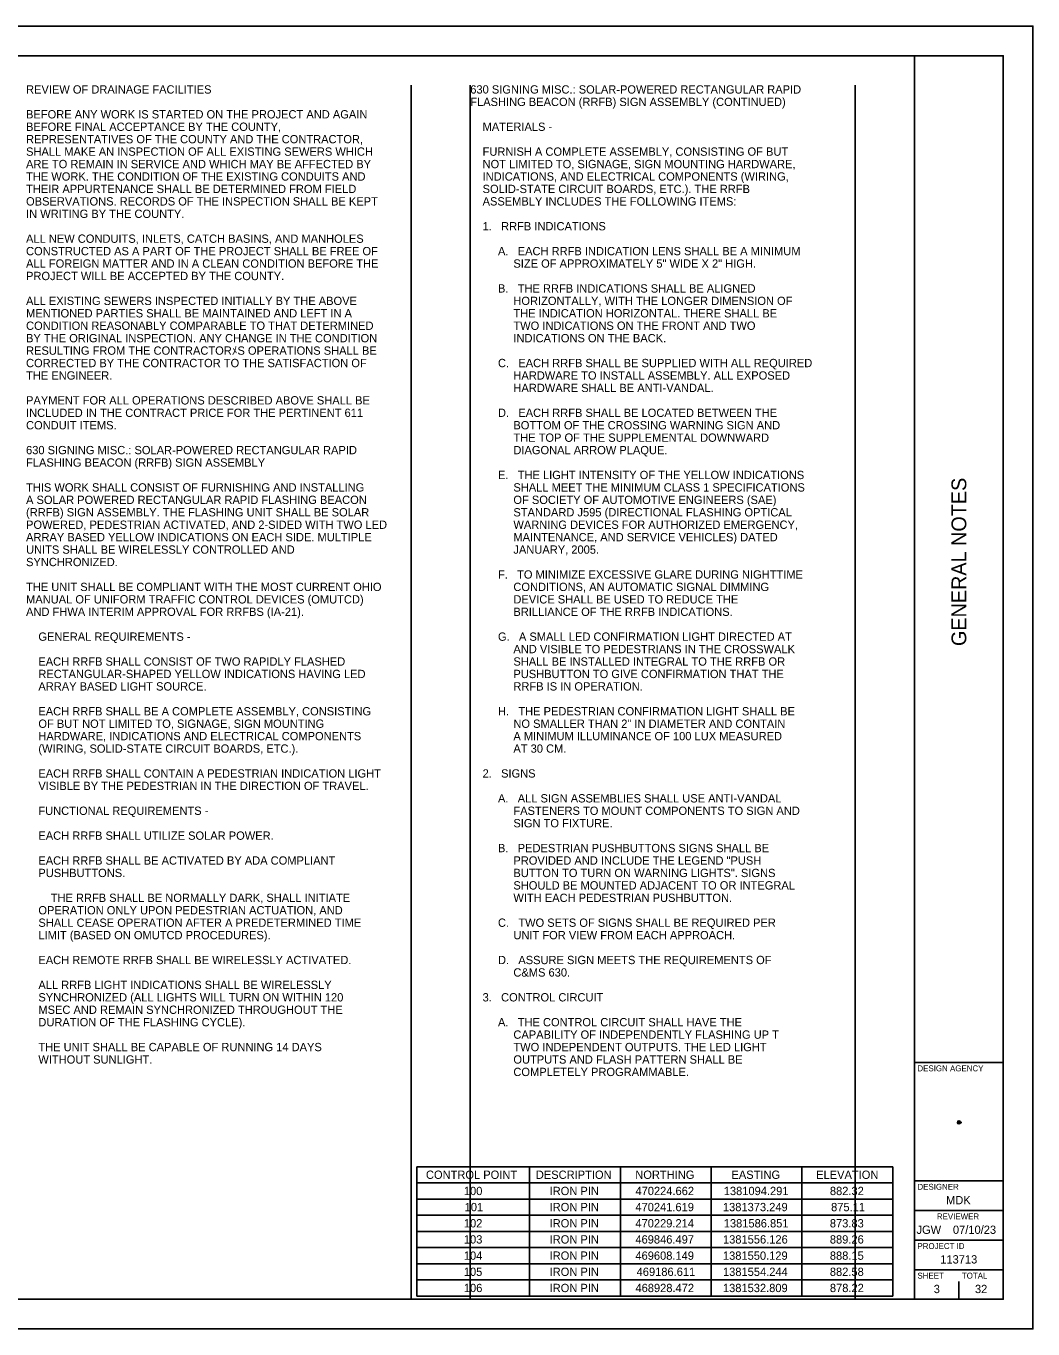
# Model space of a CAD drawing. Extents: x -8.5 to 44.5, y -22.3 to 22.
# Drawn here: x 17 to 34, y 0 to 22 of the extents above; entities that cross this region are included whole.
import ezdxf

# ---------------------------------------------------------------- set-up
doc = ezdxf.new("R2010")
doc.units = 0
for name, color, linetype in [('Default', 7, 'Continuous'), ('SN_X_Public', 7, 'Continuous'), ('SV_P_Mon_Cells_Set', 7, 'Continuous'), ('SV_X_Mon_Cells_Found', 7, 'Continuous'), ('SV_X_Random_Point', 7, 'Continuous'), ('SV_X_Shot_Marker', 7, 'Continuous')]:
    doc.layers.add(name, color=color, linetype=linetype)

msp = doc.modelspace()

# ---------------------------------------------------------------- linework, layer by layer
at = {"layer": 'Default'}
for p, q in [((32.724, 3.488), (32.776, 3.488)), ((32.75, 3.488), (32.799, 3.488))]:
    msp.add_line(p, q, dxfattribs=at)
msp.add_circle((32.75, 3.488), 0.026, dxfattribs=at)
at = {"layer": 'SN_X_Public'}
for p, q in [((23.5, 21), (23.5, 0.5)), ((24.5, 21), (24.5, 0.5)), ((31, 21), (31, 0.5))]:
    msp.add_line(p, q, dxfattribs=at)
at = {"layer": 'SV_P_Mon_Cells_Set'}
msp.add_lwpolyline([(0, 0), (34, 0), (34, 22), (0, 22)], close=True, dxfattribs=at)
at = {"layer": 'SV_X_Mon_Cells_Found'}
for p, q in [((32, 0.5), (32, 21.5)), ((32, 4.5), (33.5, 4.5)), ((32, 2.5), (33.5, 2.5)), ((32, 2), (33.5, 2)), ((32, 1.5), (33.5, 1.5)), ((32, 1), (33.5, 1))]:
    msp.add_line(p, q, dxfattribs=at)
msp.add_lwpolyline([(1.5, 21.5), (33.5, 21.5), (33.5, 0.5), (1.5, 0.5)], close=True, dxfattribs=at)
at = {"layer": 'SV_X_Random_Point'}
for p, q in [((23.6, 2.74), (31.633, 2.74)), ((23.6, 2.74), (23.6, 0.556)), ((25.5, 2.74), (25.5, 0.556)), ((27.034, 2.74), (27.034, 0.556)), ((28.566, 2.74), (28.566, 0.556)), ((30.099, 2.74), (30.099, 0.556)), ((31.633, 2.74), (31.633, 0.556)), ((23.6, 2.467), (31.633, 2.467)), ((23.6, 2.194), (31.633, 2.194)), ((23.6, 1.921), (31.633, 1.921)), ((23.6, 1.648), (31.633, 1.648)), ((23.6, 1.375), (31.633, 1.375)), ((23.6, 1.102), (31.633, 1.102)), ((23.6, 0.829), (31.633, 0.829)), ((23.6, 0.556), (31.633, 0.556))]:
    msp.add_line(p, q, dxfattribs=at)
at = {"layer": 'SV_X_Shot_Marker'}
for p, q in [((32.75, 3.5), (32.75, 3.5)), ((32.375, 0.675), (32.375, 0.675)), ((32.75, 0.5), (32.75, 0.8))]:
    msp.add_line(p, q, dxfattribs=at)

# ---------------------------------------------------------------- texts
at = {"layer": 'Default'}
for s, p in [('1', (32.749, 3.495)), ('3', (32.749, 3.478)), ('Drawing', (32.782, 3.495)), ('1:1', (32.782, 3.478))]:
    msp.add_text(s, height=0.00328, dxfattribs=at).set_placement(p)
at = {"layer": 'SV_X_Random_Point'}
for s, p in [('REVIEW OF DRAINAGE FACILITIES', (17, 20.86)), ('630 SIGNING MISC.: SOLAR-POWERED RECTANGULAR RAPID', (24.5, 20.86)), ('FLASHING BEACON (RRFB) SIGN ASSEMBLY (CONTINUED)', (24.5, 20.65)), ('BEFORE ANY WORK IS STARTED ON THE PROJECT AND AGAIN ', (17, 20.44)), ('BEFORE FINAL ACCEPTANCE BY THE COUNTY, ', (17, 20.23)), ('    MATERIALS -', (24.5, 20.23)), ('REPRESENTATIVES OF THE COUNTY AND THE CONTRACTOR, ', (17, 20.02)), ('SHALL MAKE AN INSPECTION OF ALL EXISTING SEWERS WHICH ', (17, 19.81)), ('    FURNISH A COMPLETE ASSEMBLY, CONSISTING OF BUT', (24.5, 19.81)), ('ARE TO REMAIN IN SERVICE AND WHICH MAY BE AFFECTED BY ', (17, 19.6)), ('    NOT LIMITED TO, SIGNAGE, SIGN MOUNTING HARDWARE,', (24.5, 19.6)), ('THE WORK. THE CONDITION OF THE EXISTING CONDUITS AND ', (17, 19.39)), ('    INDICATIONS, AND ELECTRICAL COMPONENTS (WIRING,', (24.5, 19.39)), ('THEIR APPURTENANCE SHALL BE DETERMINED FROM FIELD ', (17, 19.18)), ('    SOLID-STATE CIRCUIT BOARDS, ETC.). THE RRFB', (24.5, 19.18)), ('OBSERVATIONS. RECORDS OF THE INSPECTION SHALL BE KEPT ', (17, 18.97)), ('    ASSEMBLY INCLUDES THE FOLLOWING ITEMS:', (24.5, 18.97)), ('IN WRITING BY THE COUNTY.', (17, 18.76)), ('ALL NEW CONDUITS, INLETS, CATCH BASINS, AND MANHOLES ', (17, 18.34)), ('    1.   RRFB INDICATIONS', (24.5, 18.55)), ('CONSTRUCTED AS A PART OF THE PROJECT SHALL BE FREE OF ', (17, 18.13)), ('         A.   EACH RRFB INDICATION LENS SHALL BE A MINIMUM', (24.5, 18.13)), ('ALL FOREIGN MATTER AND IN A CLEAN CONDITION BEFORE THE ', (17, 17.92)), ('              SIZE OF APPROXIMATELY 5" WIDE X 2" HIGH.', (24.5, 17.92)), ('PROJECT WILL BE ACCEPTED BY THE COUNTY.', (17, 17.71)), ('         B.   THE RRFB INDICATIONS SHALL BE ALIGNED', (24.5, 17.5)), ('ALL EXISTING SEWERS INSPECTED INITIALLY BY THE ABOVE ', (17, 17.29)), ('              HORIZONTALLY, WITH THE LONGER DIMENSION OF', (24.5, 17.29)), ('MENTIONED PARTIES SHALL BE MAINTAINED AND LEFT IN A ', (17, 17.08)), ('              THE INDICATION HORIZONTAL. THERE SHALL BE', (24.5, 17.08)), ('CONDITION REASONABLY COMPARABLE TO THAT DETERMINED ', (17, 16.87)), ('              TWO INDICATIONS ON THE FRONT AND TWO', (24.5, 16.87)), ('BY THE ORIGINAL INSPECTION. ANY CHANGE IN THE CONDITION ', (17, 16.66)), ('              INDICATIONS ON THE BACK.', (24.5, 16.66)), ('RESULTING FROM THE CONTRACTORﾒS OPERATIONS SHALL BE ', (17, 16.45)), ('CORRECTED BY THE CONTRACTOR TO THE SATISFACTION OF ', (17, 16.24)), ('         C.   EACH RRFB SHALL BE SUPPLIED WITH ALL REQUIRED', (24.5, 16.24)), ('THE ENGINEER.', (17, 16.03)), ('              HARDWARE TO INSTALL ASSEMBLY. ALL EXPOSED', (24.5, 16.03)), ('              HARDWARE SHALL BE ANTI-VANDAL.', (24.5, 15.82)), ('PAYMENT FOR ALL OPERATIONS DESCRIBED ABOVE SHALL BE ', (17, 15.61)), ('INCLUDED IN THE CONTRACT PRICE FOR THE PERTINENT 611 ', (17, 15.4)), ('         D.   EACH RRFB SHALL BE LOCATED BETWEEN THE', (24.5, 15.4)), ('CONDUIT ITEMS.', (17, 15.19)), ('              BOTTOM OF THE CROSSING WARNING SIGN AND', (24.5, 15.19)), ('              THE TOP OF THE SUPPLEMENTAL DOWNWARD', (24.5, 14.98)), ('630 SIGNING MISC.: SOLAR-POWERED RECTANGULAR RAPID', (17, 14.77)), ('              DIAGONAL ARROW PLAQUE.', (24.5, 14.77)), ('FLASHING BEACON (RRFB) SIGN ASSEMBLY', (17, 14.56)), ('         E.   THE LIGHT INTENSITY OF THE YELLOW INDICATIONS', (24.5, 14.35)), ('THIS WORK SHALL CONSIST OF FURNISHING AND INSTALLING', (17, 14.14)), ('              SHALL MEET THE MINIMUM CLASS 1 SPECIFICATIONS', (24.5, 14.14)), ('A SOLAR POWERED RECTANGULAR RAPID FLASHING BEACON', (17, 13.93)), ('(RRFB) SIGN ASSEMBLY. THE FLASHING UNIT SHALL BE SOLAR', (17, 13.72)), ('              OF SOCIETY OF AUTOMOTIVE ENGINEERS (SAE)', (24.5, 13.93)), ('              STANDARD J595 (DIRECTIONAL FLASHING OPTICAL', (24.5, 13.72)), ('POWERED, PEDESTRIAN ACTIVATED, AND 2-SIDED WITH TWO LED', (17, 13.51)), ('              WARNING DEVICES FOR AUTHORIZED EMERGENCY,', (24.5, 13.51)), ('ARRAY BASED YELLOW INDICATIONS ON EACH SIDE. MULTIPLE', (17, 13.3)), ('              MAINTENANCE, AND SERVICE VEHICLES) DATED', (24.5, 13.3)), ('UNITS SHALL BE WIRELESSLY CONTROLLED AND ', (17, 13.09)), ('              JANUARY, 2005.', (24.5, 13.09)), ('SYNCHRONIZED.', (17, 12.88)), ('         F.   TO MINIMIZE EXCESSIVE GLARE DURING NIGHTTIME', (24.5, 12.67)), ('THE UNIT SHALL BE COMPLIANT WITH THE MOST CURRENT OHIO', (17, 12.46)), ('              CONDITIONS, AN AUTOMATIC SIGNAL DIMMING', (24.5, 12.46)), ('MANUAL OF UNIFORM TRAFFIC CONTROL DEVICES (OMUTCD)', (17, 12.25)), ('              DEVICE SHALL BE USED TO REDUCE THE', (24.5, 12.25)), ('AND FHWA INTERIM APPROVAL FOR RRFBS (IA-21).', (17, 12.04)), ('              BRILLIANCE OF THE RRFB INDICATIONS.', (24.5, 12.04)), ('    GENERAL REQUIREMENTS -', (17, 11.62)), ('         G.   A SMALL LED CONFIRMATION LIGHT DIRECTED AT', (24.5, 11.62)), ('              AND VISIBLE TO PEDESTRIANS IN THE CROSSWALK', (24.5, 11.41)), ('    EACH RRFB SHALL CONSIST OF TWO RAPIDLY FLASHED', (17, 11.2)), ('              SHALL BE INSTALLED INTEGRAL TO THE RRFB OR', (24.5, 11.2)), ('    RECTANGULAR-SHAPED YELLOW INDICATIONS HAVING LED', (17, 10.99)), ('              PUSHBUTTON TO GIVE CONFIRMATION THAT THE', (24.5, 10.99)), ('    ARRAY BASED LIGHT SOURCE.', (17, 10.78)), ('              RRFB IS IN OPERATION.', (24.5, 10.78)), ('    EACH RRFB SHALL BE A COMPLETE ASSEMBLY, CONSISTING', (17, 10.36)), ('         H.   THE PEDESTRIAN CONFIRMATION LIGHT SHALL BE', (24.5, 10.36)), ('    OF BUT NOT LIMITED TO, SIGNAGE, SIGN MOUNTING', (17, 10.15)), ('              NO SMALLER THAN 2" IN DIAMETER AND CONTAIN', (24.5, 10.15)), ('    HARDWARE, INDICATIONS AND ELECTRICAL COMPONENTS', (17, 9.94)), ('              A MINIMUM ILLUMINANCE OF 100 LUX MEASURED', (24.5, 9.94)), ('    (WIRING, SOLID-STATE CIRCUIT BOARDS, ETC.).', (17, 9.73)), ('              AT 30 CM.', (24.5, 9.73)), ('    VISIBLE BY THE PEDESTRIAN IN THE DIRECTION OF TRAVEL.', (17, 9.1)), ('    EACH RRFB SHALL CONTAIN A PEDESTRIAN INDICATION LIGHT', (17, 9.31)), ('    2.   SIGNS', (24.5, 9.31)), ('         A.   ALL SIGN ASSEMBLIES SHALL USE ANTI-VANDAL', (24.5, 8.89)), ('    FUNCTIONAL REQUIREMENTS -', (17, 8.68)), ('              FASTENERS TO MOUNT COMPONENTS TO SIGN AND', (24.5, 8.68)), ('              SIGN TO FIXTURE.', (24.5, 8.47)), ('    EACH RRFB SHALL UTILIZE SOLAR POWER.', (17, 8.26)), ('         B.   PEDESTRIAN PUSHBUTTONS SIGNS SHALL BE', (24.5, 8.05)), ('    EACH RRFB SHALL BE ACTIVATED BY ADA COMPLIANT', (17, 7.84)), ('              PROVIDED AND INCLUDE THE LEGEND "PUSH', (24.5, 7.84)), ('    PUSHBUTTONS.', (17, 7.63)), ('              BUTTON TO TURN ON WARNING LIGHTS". SIGNS', (24.5, 7.63)), ('              SHOULD BE MOUNTED ADJACENT TO OR INTEGRAL', (24.5, 7.42)), ('        THE RRFB SHALL BE NORMALLY DARK, SHALL INITIATE', (17, 7.21)), ('              WITH EACH PEDESTRIAN PUSHBUTTON.', (24.5, 7.21)), ('    OPERATION ONLY UPON PEDESTRIAN ACTUATION, AND', (17, 7)), ('    SHALL CEASE OPERATION AFTER A PREDETERMINED TIME', (17, 6.79)), ('         C.   TWO SETS OF SIGNS SHALL BE REQUIRED PER', (24.5, 6.79)), ('    LIMIT (BASED ON OMUTCD PROCEDURES).', (17, 6.58)), ('              UNIT FOR VIEW FROM EACH APPROACH.', (24.5, 6.58)), ('    EACH REMOTE RRFB SHALL BE WIRELESSLY ACTIVATED.', (17, 6.16)), ('         D.   ASSURE SIGN MEETS THE REQUIREMENTS OF', (24.5, 6.16)), ('              C&MS 630.', (24.5, 5.95)), ('    ALL RRFB LIGHT INDICATIONS SHALL BE WIRELESSLY', (17, 5.74)), ('    SYNCHRONIZED (ALL LIGHTS WILL TURN ON WITHIN 120', (17, 5.53)), ('    3.   CONTROL CIRCUIT', (24.5, 5.53)), ('    MSEC AND REMAIN SYNCHRONIZED THROUGHOUT THE', (17, 5.32)), ('    DURATION OF THE FLASHING CYCLE).', (17, 5.11)), ('         A.   THE CONTROL CIRCUIT SHALL HAVE THE', (24.5, 5.11)), ('              CAPABILITY OF INDEPENDENTLY FLASHING UP T', (24.5, 4.9)), ('    WITHOUT SUNLIGHT.', (17, 4.48)), ('    THE UNIT SHALL BE CAPABLE OF RUNNING 14 DAYS', (17, 4.69)), ('              TWO INDEPENDENT OUTPUTS. THE LED LIGHT', (24.5, 4.69)), ('              OUTPUTS AND FLASH PATTERN SHALL BE', (24.5, 4.48)), ('              COMPLETELY PROGRAMMABLE.', (24.5, 4.27)), ('CONTROL POINT', (23.752, 2.534)), ('DESCRIPTION', (25.607, 2.534)), ('NORTHING', (27.286, 2.534)), ('EASTING', (28.91, 2.534)), ('ELEVATION', (30.34, 2.534)), ('100', (24.392, 2.26)), ('IRON PIN', (25.84, 2.26)), ('470224.662', (27.289, 2.26)), ('1381094.291', (28.78, 2.26)), ('882.32', (30.572, 2.26)), ('101', (24.405, 1.988)), ('IRON PIN', (25.84, 1.988)), ('470241.619', (27.288, 1.988)), ('1381373.249', (28.766, 1.988)), ('875.11', (30.592, 1.988)), ('102', (24.392, 1.714)), ('IRON PIN', (25.84, 1.714)), ('470229.214', (27.288, 1.714)), ('1381586.851', (28.78, 1.714)), ('873.83', (30.571, 1.714)), ('103', (24.392, 1.442)), ('IRON PIN', (25.84, 1.442)), ('469846.497', (27.288, 1.442)), ('1381556.126', (28.767, 1.442)), ('889.26', (30.571, 1.442)), ('104', (24.392, 1.168)), ('IRON PIN', (25.84, 1.168)), ('469608.149', (27.288, 1.168)), ('1381550.129', (28.766, 1.168)), ('888.15', (30.571, 1.168)), ('105', (24.391, 0.895)), ('IRON PIN', (25.84, 0.895)), ('469186.611', (27.309, 0.895)), ('1381554.244', (28.767, 0.895)), ('882.58', (30.571, 0.895)), ('106', (24.392, 0.622)), ('IRON PIN', (25.84, 0.622)), ('468928.472', (27.289, 0.622)), ('1381532.809', (28.766, 0.622)), ('878.22', (30.572, 0.622))]:
    msp.add_text(s, height=0.14, dxfattribs=at).set_placement(p)
at = {"layer": 'SV_X_Shot_Marker'}
msp.add_text('GENERAL NOTES', height=0.25, rotation=90, dxfattribs=at).set_placement((32.875, 11.531))
for s, height, p in [('DESIGN AGENCY', 0.1, (32.05, 4.35)), ('DESIGNER', 0.1, (32.05, 2.35)), ('MDK', 0.14, (32.533, 2.105)), ('REVIEWER', 0.1, (32.378, 1.85)), ('JGW', 0.14, (32.034, 1.605)), ('07/10/23', 0.14, (32.649, 1.605)), ('PROJECT ID', 0.1, (32.05, 1.35)), ('113713', 0.14, (32.435, 1.105)), ('SHEET', 0.1, (32.05, 0.85)), ('TOTAL', 0.1, (32.8, 0.85)), ('3', 0.14, (32.325, 0.605)), ('32', 0.14, (33.021, 0.605))]:
    msp.add_text(s, height=height, dxfattribs=at).set_placement(p)

doc.saveas('drawing.dxf')
